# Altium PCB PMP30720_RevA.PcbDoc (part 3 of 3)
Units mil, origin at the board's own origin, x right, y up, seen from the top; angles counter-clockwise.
Board outline 4575 x 5400 mil, 4 copper layers (Top Layer, Signal Layer 1, Signal Layer 2, Bottom Layer), stack 61.6 mil thick; 223 components, 107 nets, 514 pads, 63 vias.
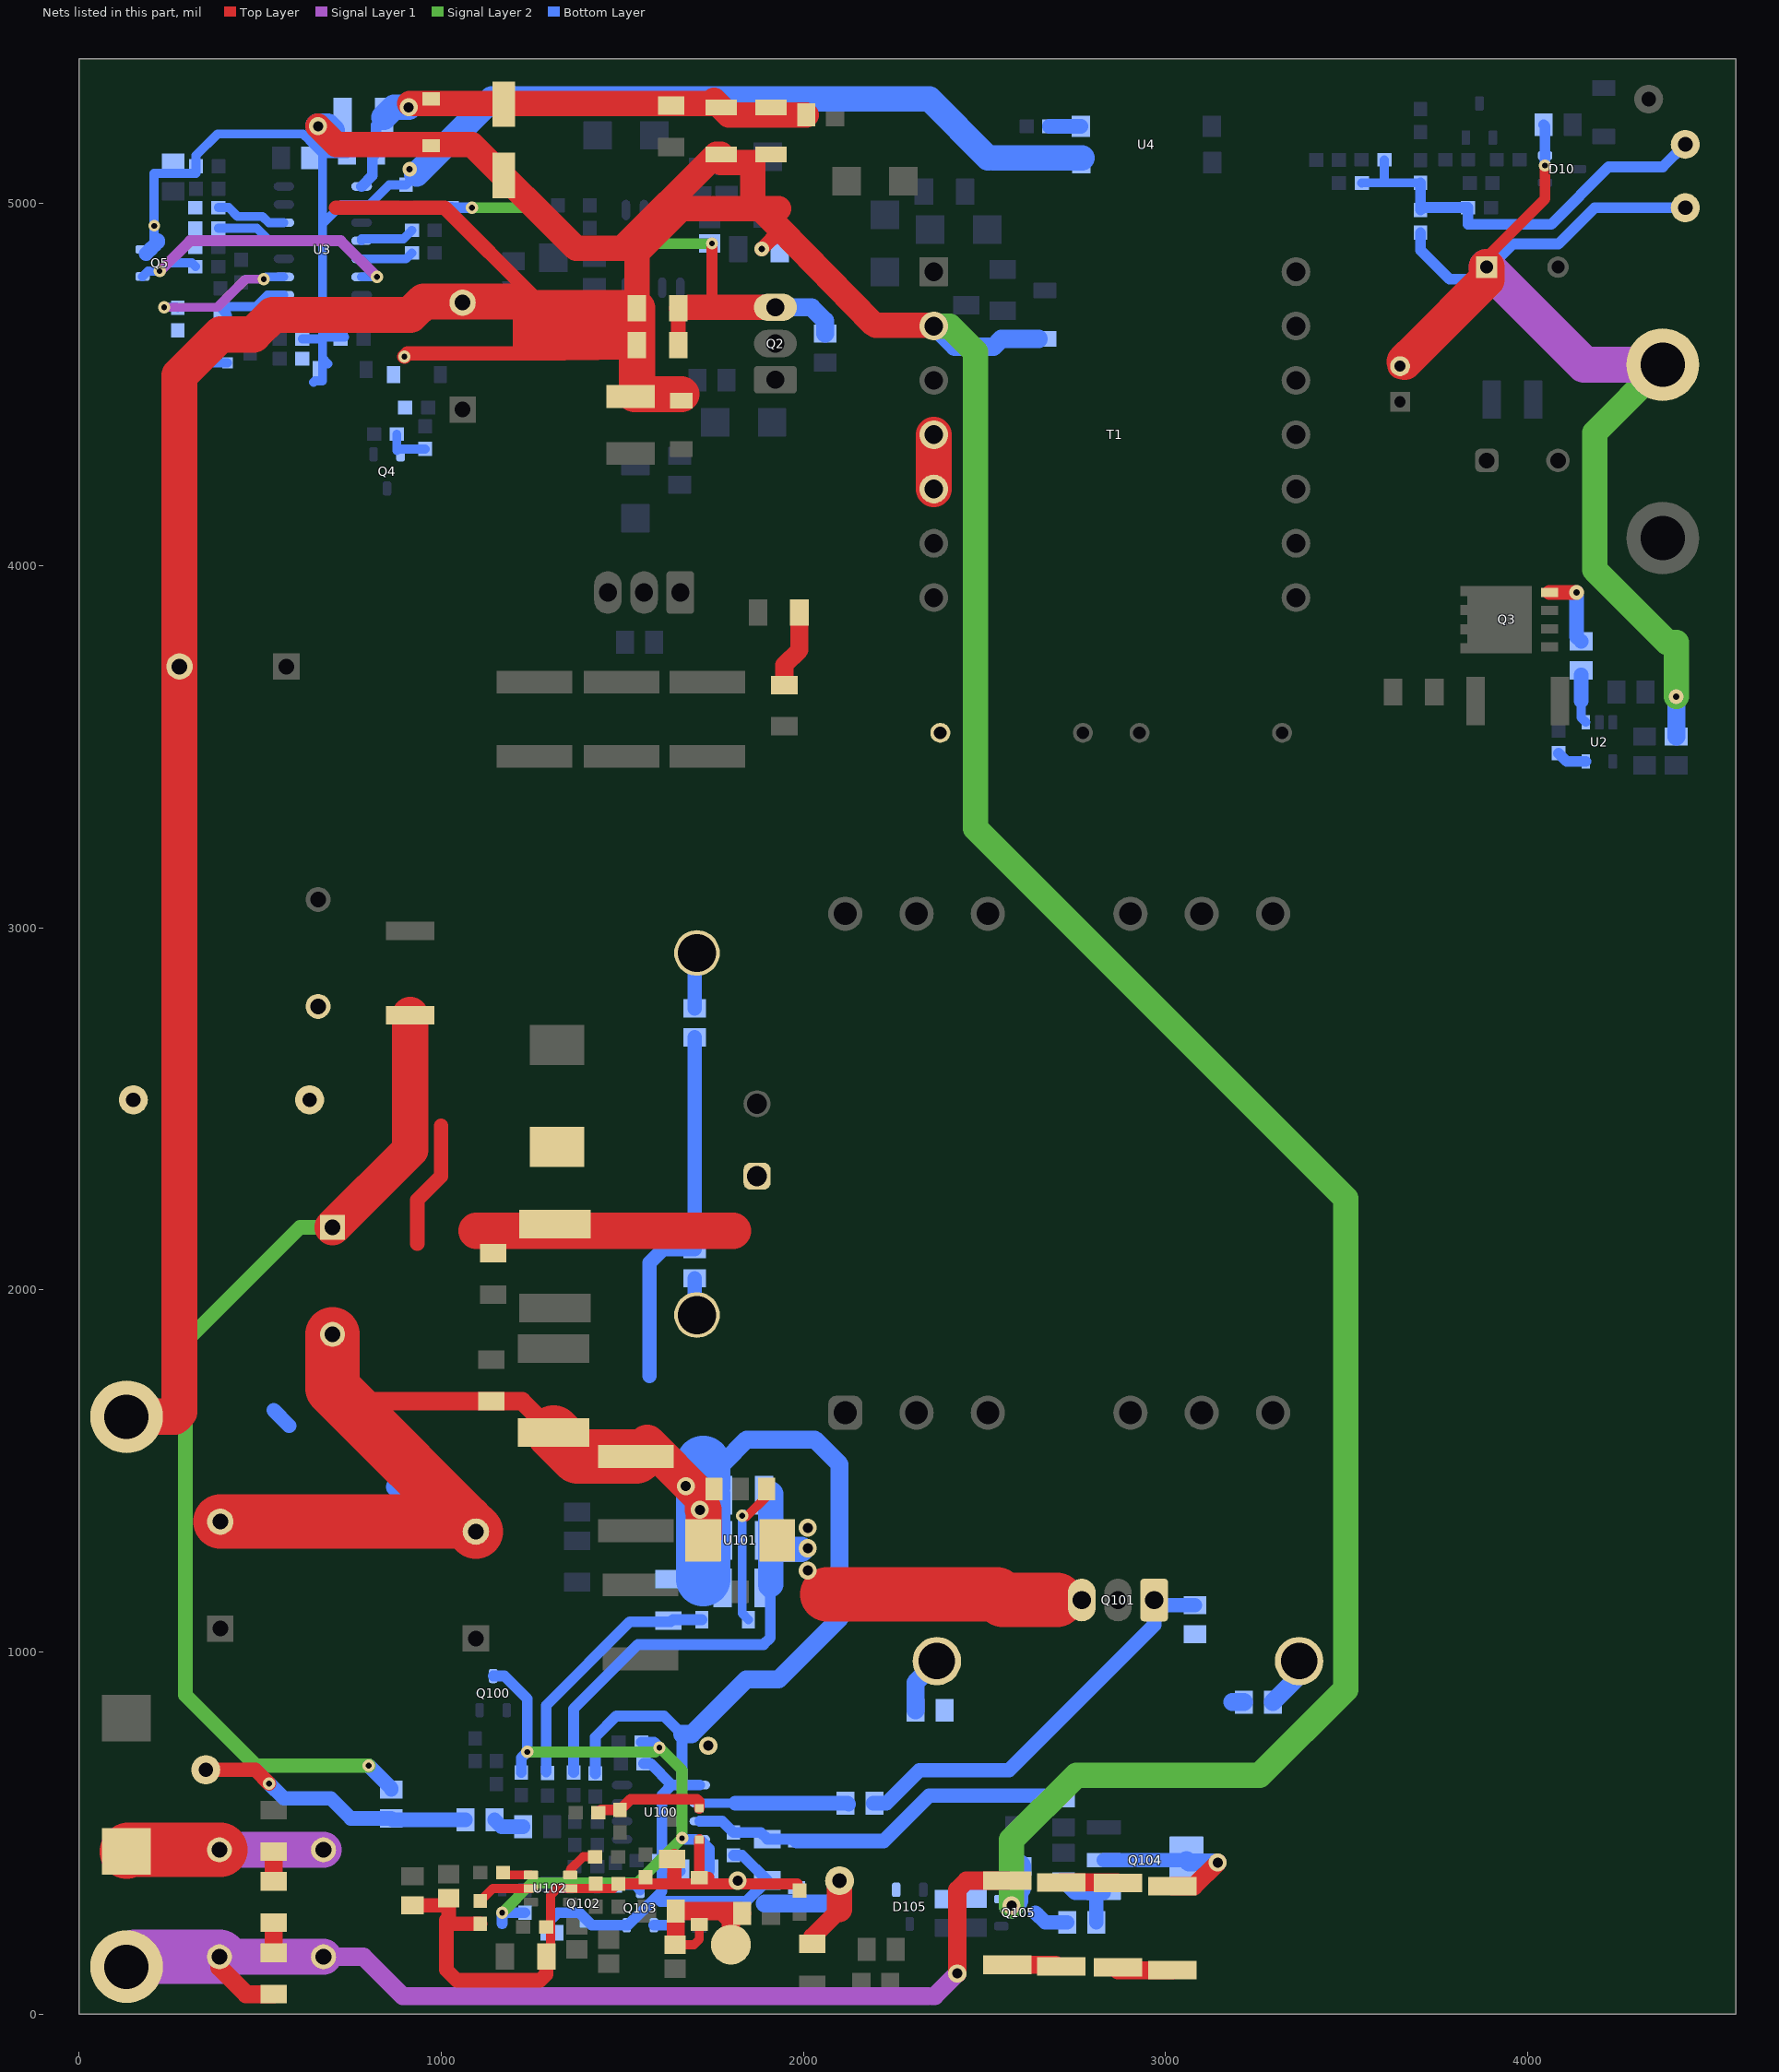
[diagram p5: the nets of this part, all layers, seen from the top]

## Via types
v1: diameter 34, hole 16, Top Layer to Bottom Layer, 36 vias
v2: diameter 50, hole 28, Top Layer to Bottom Layer, 21 vias
v3: diameter 40, hole 18, Top Layer to Bottom Layer, 5 vias
v4: diameter 32, hole 16, Top Layer to Bottom Layer, 1 vias

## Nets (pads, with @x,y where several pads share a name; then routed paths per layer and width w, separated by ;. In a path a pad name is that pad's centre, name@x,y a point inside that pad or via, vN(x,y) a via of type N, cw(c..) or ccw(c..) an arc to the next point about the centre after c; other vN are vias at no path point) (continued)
NetD104_1: D104.1 R124.2 R126.2 | length 710.7
  Bottom Layer w30: R124.2@1290.11,669.37 1290.11,852.63 1520.9,1083.43 1633.86,1083.43 1640.11,1089.68 D104.1@1719.39,1089.68
NetD104_2: D104.2 U101.1 | length 400.8
  Top Layer w25: v1@1843.54,1374.78 1898.54,1429.78 U101.1@1898.54,1450.16
  Bottom Layer w25: v1@1834.72,1380.28 v1(1831.03,1376.59) 1831.03,1106.98 D104.2@1848.33,1089.68 ; v1@1834.73,1380.26 v1@1838.07,1380.26
NetD106_1: D106.1 R138.1 R141.2 | length 315.5
  Top Layer w30: R138.1@1433.98,556.25 1442.02,564.29 R141.2@1493.75,564.29 1523.21,593.75 1706.25,593.75 1712.5,587.5 D106.1@1712.5,568.62
NetD107_1: D107.1 R142.1 R145.2 R146.1 TP104.1 | length 524.7
  Top Layer w25: R142.1@1645.62,192.08 1698.33,192.08 1712.5,206.25 D107.1@1712.5,248.03
  Top Layer w50: R142.1@1645.62,192.08 1648.12,194.58 R145.2@1648.12,284.69 1775,284.69 ; TP104.1@1781.25,171.36 1800,190.11 TP104.1@1800,192.08 1800,259.69 1775,284.69 ; R146.1@1830.62,278.44 1824.37,284.69 1775,284.69
NetF100_2: F100.2 RT100.2 RT101.2 | length 548.3
  Top Layer w150: F100.2@131.25,449.37 135.77,453.89 RT100.2@387.5,453.89 RT100.2@390.18,453.89
  Signal Layer 1 w100: RT100.2@387.5,453.89 RT101.2@675,453.89
NetH100_1: H100.1 R101.2 | length 122.9
  Bottom Layer w40: R101.2@1700,2777.5 1700,2893.72 H100.1@1704.75,2898.47
NetH100_2: H100.2 R100.2 | length 136
  Bottom Layer w40: R100.2@1700,2032.5 1700,1903.22 H100.2@1704.75,1898.47
NetH101_1: H101.1 R116.2 | length 159.9
  Bottom Layer w50: R116.2@2309.78,839.52 2309.78,916.03 H101.1@2368.75,975
NetH101_2: H101.2 R117.2 | length 143.4
  Bottom Layer w50: R117.2@3296.03,861.77 3368.75,934.49 H101.2@3368.75,975
NetQ2_3: Q2.3 R8.1 R9.2 R13.2 R14.2 R29.1 | length 1495.3
  Top Layer w30: 1747.64,4713.47 v1(1747.64,4890)
  Top Layer w40: R14.2@1654.72,4609.19 R13.2@1654.72,4710.77
  Top Layer w50: R13.2@1654.72,4710.77 1657.42,4713.47 1685.14,4713.47
  Top Layer w70: 1685.14,4713.47 1747.64,4713.47 Q2.3@1922.64,4713.47
  Signal Layer 2 w30: v1(1085.14,4988.47) 1235.14,4988.47 1335.14,4888.47 v1(1747.64,4890)
  Bottom Layer w30: R29.1@1029.13,4988.91 1029.58,4988.47 v1(1085.14,4988.47)
  Bottom Layer w50: Q2.3@1922.64,4713.47 2022.64,4713.47 2060.14,4675.97 R8.1@2060.14,4640.97
NetQ3_4: Q3.4 R18.2 | length 215.3
  Top Layer w40: Q3.4@4060.02,3925.97 v3(4135.14,3925.97)
  Bottom Layer w40: v3(4135.14,3925.97) 4135.14,3803.47 R18.2@4147.64,3790.97
NetQ4_2: Q4.2 R26.1 R34.2 | length 125.6
  Bottom Layer w25: R26.1@877.49,4363.47 877.49,4317.96 881.93,4322.4 R34.2@955.76,4322.4
NetQ5_1: Q5.1 U3.6 | length 776.2
  Signal Layer 1 w30: v1(222.64,4813.47) 306.51,4897.34 722.64,4897.34 v1(822.64,4797.34)
  Bottom Layer w25: Q5.1@175.39,4798.6 190.26,4813.47 v1(222.64,4813.47) v1@219.59,4810.41 ; U3.6@780.27,4797.34 v1(822.64,4797.34)
NetQ5_3: Q5.3 R35.1 | length 65.7
  Bottom Layer w25: Q5.3@260.04,4836.01 311.59,4836.01 R35.1@321.62,4825.97
NetQ101_1: Q101.1 R110.2 R113.2 | length 1167.1
  Bottom Layer w40: R110.2@2192.61,582.8 R110.2@2196.03,582.8 2229.24,582.8 2320.33,673.89 2567.64,673.89 2968.75,1075 Q101.1@2968.75,1143.75 2982.82,1129.68 R113.2@3081.25,1129.68
NetQ101_3: Q101.3 R120.2 R127.2 R128.2 R129.2 U101.8 | length 1981.4
  Top Layer w70: 2700,1143.75 Q101.3@2768.75,1143.75
  Top Layer w150: 2065.97,1159.7 2534.72,1159.7 2550.67,1143.75 2700,1143.75
  Bottom Layer w30: R120.2@1365.57,667.4 1365.57,843.02 1543.48,1020.93 1890.11,1020.93 1908.86,1039.68 1908.86,1159.26 R127.2@1890.95,1177.18
  Bottom Layer w70: R127.2@1910.28,1186.77 R129.2@1910.28,1436.77 ; R128.2@1916.8,1283.43 v2@1993.53,1283.43
  other v2: 2012.28,1225.06 2012.28,1286.77 2012.28,1343.02
NetQ103_1: Q103.1 R119.1 | length 63.5
  Bottom Layer w30: Q103.1@1587.18,245.77 1646.77,245.77 R119.1@1649.53,243.02
NetQ103_3: Q103.3 R115.1 | length 75
  Bottom Layer w25: R115.1@1481.03,355.27 1534.77,355.27 Q103.3@1549.78,340.26
NetQ104_1: Q104.1 R131.1 R133.2 | length 217.4
  Bottom Layer w40: R133.2@2718.75,366.25 2749.97,335.03 Q104.1@2829.58,335.03 ccw(c2829.58,314.2) 2808.75,314.2 R131.1@2808.75,253.31
NetQ104_2: Q104.2 Q104.4 R130.1 | length 469
  Top Layer w50: R130.1@3018.75,353.64 3078.64,353.64 v2(3143.75,418.75)
  Bottom Layer w40: Q104.2@2829.58,425.58 Q104.4@3057.92,425.58
  Bottom Layer w50: Q104.4@3057.92,425.58 3064.75,418.75 v2(3143.75,418.75)
NetQ105_3: Q105.3 R131.2 | length 99
  Bottom Layer w40: Q105.3@2640.99,280.52 2668.2,253.31 R131.2@2728.75,253.31
NetR1_1: R1.1 R2.2 | length 217.5
  Top Layer w50: R1.1@1947.64,3670.55 1947.64,3725.97 1988.98,3767.31 R2.2@1988.98,3870.92
NetR18_1: R18.1 U2.1 | length 136.1
  Bottom Layer w25: 4147.64,3626.06 4147.64,3580.2 U2.1@4160.24,3567.6
  Bottom Layer w40: 4147.64,3626.06 R18.1@4147.64,3698.47
NetR19_1: R19.1 U2.5 | length 84.5
  Bottom Layer w30: R19.1@4085.14,3481.97 4107.78,3459.33 U2.5@4160.24,3459.33
NetR23_1: R23.1 R28.2 R30.2 R31.2 R32.2 TP6.1 | length 1174.5
  Bottom Layer w25: R31.2@3541.63,5056.78 3542.08,5057.23 3597.64,5057.23 ; R28.2@3604.13,5120.63 3604.13,5063.73 3597.64,5057.23 ; R32.2@3704.13,5057.23 3597.64,5057.23
  Bottom Layer w30: R32.2@3704.13,5057.23 R23.1@3704.13,4982.46 3710.59,4988.91 R30.2@3835.14,4988.91 3835.14,4942.97 4065.13,4942.97 4223.44,5101.28 4372.95,5101.28 TP6.1@4435.14,5163.47
NetR25_2: R25.2 R40.1 U3.10 | length 301.9
  Bottom Layer w25: R40.1@410.14,4616.47 410.14,4691.84 386.13,4715.84 488.7,4715.84 520.2,4747.34 U3.10@565.7,4747.34
NetR33_1: R33.1 U4.4 | length 86.9
  Bottom Layer w40: R33.1@2679.13,5213.47 U4.4@2766.04,5213.47
NetR37_2: R37.2 U3.13 | length 195.7
  Bottom Layer w25: R37.2@384.62,4931.97 384.62,4931.59 491.04,4931.59 525.29,4897.34 U3.13@565.7,4897.34
NetR38_2: R38.2 U3.14 | length 198.3
  Bottom Layer w25: R38.2@384.62,4988.91 413.32,4988.91 437.77,4964.46 506.64,4964.46 523.77,4947.34 U3.14@565.7,4947.34
NetR105_1: R105.1 R107.2 TP101.1 | length 774.8
  Top Layer w40: TP101.1@350,675 487.1,675 v1(525,637.1)
  Bottom Layer w40: v1(525,637.1) 565.7,596.4 694.59,596.4 750.47,540.52 R105.1@862.28,540.52 866.03,536.77 R107.2@1067.51,536.77
NetR107_1: R107.1 R108.2 | length 86.3
  Bottom Layer w40: R107.1@1147.51,536.77 1166.26,518.02 R108.2@1226.06,518.02
NetR110_1: R110.1 U100.6 | length 412.2
  Bottom Layer w25: U100.6@1714.1,582.8 1811.76,582.8
  Bottom Layer w40: 1811.76,582.8 2122.21,582.8 R110.1@2125.11,579.9
NetR112_1: R112.1 R118.2 | length 127.9
  Top Layer w50: R112.1@2568.24,136.07 R118.2@2696.19,136.07
NetR118_1: R118.1 R123.2 | length 157.1
  Top Layer w50: R118.1@2712.5,364.17 2866.68,364.17 R123.2@2868.75,362.11
NetR123_1: R123.1 R130.2 | length 150
  Top Layer w50: R123.1@2868.75,121.36 R130.2@3018.75,121.36
NetR132_1: R132.1 R137.2 | length 83.2
  Top Layer w50: R132.1@537.2,169.59 537.2,252.41 R137.2@537.5,252.71
NetR137_1: R137.1 R140.2 | length 82.3
  Top Layer w50: R137.1@537.5,366.88 R140.2@537.5,449.16
NetR139_2: R139.2 U102.5 | length 154.1
  Top Layer w25: R139.2@1107.87,312.75 1142.32,347.19 U102.5@1247.74,347.19
NetR144_2: R144.2 U102.3 | length 98.1
  Top Layer w25: U102.3@1356,384.6 1356,398.75 1391.95,434.69 R144.2@1425.05,434.69
NetR147_2: R147.2 U102.4 | length 79.5
  Top Layer w25: R147.2@1170.87,390.94 1177.21,384.6 U102.4@1247.74,384.6
NetRT2_2: RT2.2 U3.11 | length 403.1
  Signal Layer 1 w25: v1(235.14,4713.47) 382.09,4713.47 459.8,4791.18 v1(510.14,4791.18)
  Bottom Layer w25: v1(235.14,4713.47) 271.51,4713.47 RT2.2@272.54,4712.44 ; v1(510.14,4791.18) 516.3,4797.34 U3.11@565.7,4797.34
NetT1_4: T1.4 T1.5 | length 150
  Top Layer w100: T1.5@2360.14,4211.78 T1.4@2360.14,4361.78
PGND: C1.2 C2.2 C3.2 C4.2 C17.2 C18.2 C19.2 C20.2 C21.2 C23.2 C27.1 C28.2 C31.2 C32.2 C34.2 C35.2 C36.2 C37.2 C38.2 C100.2 C101.2 C104.2 C105.2 C106.2 C107.2 C108.2 C112.2 C113.2 C114.2 C115.2 C116.2 C117.2 C118.2 C119.2 C120.2 C121.2 C122.2 C123.2 C124.2 D9.2 D102.2 D105.1 D106.2 D107.2 DZ1.2 Dz2.2 Q5.2 Q102.3 Q103.2 Q105.2 R10.1 R13.1 R14.1 R22.1 R37.1 R38.1 R39.1 R40.2 R100.1 R101.1 R104.1 R106.1 R113.1 R116.1 R117.1 R122.1 R126.1 R127.1 R128.1 R129.1 R139.1 R143.1 R148.1 R149.1 R150.1 RT2.1 T1.2 TP2.1 TP102.1 TP103.1 U3.2 U4.3 U100.5 U101.3 U101.7 U102.2 | length 28880.8
  Top Layer w25: C117.2@1290.21,159.69 1301.87,171.36 1301.87,328.44 1320.62,347.19 U102.2@1356,347.19 1476.62,347.19 C121.2@1489.37,359.94
  Top Layer w30: C121.2@1489.37,359.94 1739.37,359.94 ; D107.2@1712.5,378.36 D106.2@1712.5,482.01 ; 1739.37,378.2 1739.37,359.94 ; C122.2@1983.37,359.94 1739.37,359.94
  Top Layer w40: 710.14,4988.47 1010.14,4988.47 1260.14,4738.47 1260.14,4710.77 ; v1(898.38,4577.26) 907.53,4586.42 1338.83,4586.42 R14.1@1530.71,4588.47 ; R150.1@920.62,300.94 1001.58,300.94 C124.2@1020.62,319.98 1020.62,265.94 1014.37,259.69 ; R139.1@1107.87,249.75 1024.31,249.75 1014.37,259.69 ; C117.2@1290.21,159.69 1290.21,110.53 1273.43,93.75 1042.82,93.75 1014.37,122.19 1014.37,259.69 ; 1643.75,366.88 C123.2@1643.75,436.34 ; v3(1885.14,4874.43) 1934.09,4923.39 1934.09,4931.9
  Top Layer w50: 759.82,1668.72 784.01,1692.91 R106.1@1138.09,1692.91 1223.62,1692.91 C106.2@1310.28,1606.25 ; 1222.64,4597.29 1222.81,4675.94 ; C118.2@2025,194.59 2025,213.93 2100,288.93
  Top Layer w70: v2(660.14,5213.47) 710.14,5163.47 1085.14,5163.47 1372.64,4875.97 1499.21,4875.97 1759.25,5136.01 C20.2@1772.64,5136.01 ; R13.1@1540.55,4710.77 1540.55,4863.47 1663.32,4986.23 1860.14,4986.23 ; 1772.64,5113.47 1860.14,5113.47 1860.14,4986.23 ; 1874.81,4992.5 1880.94,4986.23 ; 1931.9,4986.23 1880.94,4986.23 ; 2100,288.93 TP103.1@2100,368.75 ; 2190.55,4669.74 1934.09,4931.9 1880.94,4986.23 ; 2200.88,4663.47 2358.45,4663.47 T1.2@2360.14,4661.78 ; 1860.14,4986.23 1880.94,4986.23
  Top Layer w100: TP102.1@131.25,1650 263.98,1650 277.36,1663.39 277.13,1663.39 277.13,3721.34 C1.2@277.36,3721.58 277.36,4525 390.83,4638.47 481.32,4638.47 535.14,4692.28 914.33,4692.28 951.66,4729.62 1193.99,4729.62 ; 1251.64,4650.97 1485.14,4650.97 ; 1260.14,4710.77 R13.1@1540.55,4710.77 R14.1@1540.55,4609.19 C3.2@1540.55,4485.12 ; C3.2@1534.45,4473.34 C4.2@1663.32,4473.34 ; C104.2@1537.5,1539.86 C104.2@1567.26,1539.86 ; 1569.03,1578.1 1715.88,1431.25 ; v2@1722.51,1392.97 v2@1722.53,1395.92 ; U101.7@1725,1317.67 v2@1725,1393.02
  Top Layer w150: C100.2@390.18,1360.14 1068.41,1360.14 ; C105.2@700,1877.36 700,1728.54 759.82,1668.72 1068.41,1360.14 ; C101.2@1095.87,1332.68 1068.41,1360.14 ; C106.2@1310.28,1606.25 1376.67,1539.86 C104.2@1537.5,1539.86
  Signal Layer 2 w70: T1.2@2360.14,4661.78 2403.74,4661.78 2475,4590.52 2475,3275 3497.13,2252.87 3497.13,897.13 3259.73,659.73 2753.67,659.73 2575,481.07 v2(2575,300)
  Bottom Layer w25: 201.33,4877.69 207.44,4883.8 v4(207.44,4938.47) 207.44,5083.4 323.14,5083.4 323.14,5132.97 382.38,5192.21 618.9,5192.21 637.64,5173.47 637.64,5172.47 672.64,5137.47 ; 363.44,4560.47 R40.2@410.14,4560.47 ; R22.1@616.63,4625.97 672.64,4625.97 ; 647.64,4506.67 651.67,4510.71 672.64,4510.71 672.64,4572.15 ; 686.87,4557.91 672.64,4572.15 ; C27.1@733.76,4631.04 680.06,4631.04 674.99,4625.97 672.64,4625.97 ; C34.2@740.27,5138.47 739.27,5137.47 672.64,5137.47 ; 932.38,5081.2 C38.2@903.09,5051.91 856.15,5051.91 801.57,4997.34 U3.2@780.27,4997.34 725.15,4997.34 672.64,4944.82 ; 672.64,4572.15 672.64,4625.97 ; 672.64,4625.97 672.64,4944.82 ; 672.64,4944.82 672.64,5137.47
  Bottom Layer w30: 1306.61,265.52 1321.37,280.27 1381.03,280.27 1415.52,245.77 Q103.2@1512.37,245.77 1515.67,245.77 1593.72,323.82 ; C115.2@1425.57,664.29 1425.57,765.35 1483.86,823.65 1615.11,823.65 1665.11,773.65 1665.11,632.8 ; C112.2@1559.11,692.4 1577.16,692.4 1636.76,632.8 ; C113.2@1660.57,395.3 1650.97,404.9 1609.35,404.9 ; U100.5@1714.1,632.8 1665.11,632.8 ; C107.2@1806.82,438.8 1831.23,438.8 C108.2@1900.57,369.46 1842.87,311.77 1605.78,311.77 1593.72,323.82 ; 1593.72,323.82 1609.35,339.45 1609.35,404.9 ; 1609.35,404.9 1609.35,605.39 1636.76,632.8 ; 1636.76,632.8 1665.11,632.8
  Bottom Layer w40: Q5.2@185.24,4861.6 201.33,4877.69 ; 207.44,4883.8 217.43,4893.79 217.43,4897.34 ; 537.28,1668.02 580.17,1625.12 ; 1575,1762.62 1575,2075 1612.5,2112.5 R100.1@1700,2112.5 R101.1@1700,2697.5
  Bottom Layer w50: 872.22,1456.06 1009.72,1318.56 ; 1665.11,773.65 1691.48,773.65 1842.1,924.27 1931.03,924.27 2099.78,1093.02 2099.78,1518.02 2031.03,1586.77 1843.53,1586.77 1779.21,1522.45 1723.35,1522.45 ; 1893.53,305.52 2099.93,305.3 2103.19,305.3 ; T1.2@2360.14,4661.78 2417.22,4604.69 C17.2@2450,4604.69 2525,4604.69 2546.59,4626.28 C18.2@2650,4626.28 ; 3184.27,861.77 R117.1@3216.03,861.77
  Bottom Layer w70: v2(660.14,5213.47) 686.27,5213.47 698.77,5200.97 ; 932.38,5081.2 1139.65,5288.47 2347.64,5288.47 2509.4,5125.97 ; 2525,5125.97 U4.3@2769.39,5125.97 ; v2(2575,300) 2578.12,303.12 2578.12,306.56 2585.78,314.22 2585.78,327.75 2578.93,334.6 2593.75,349.41 C119.2@2593.75,407.88
  Bottom Layer w150: 1723.35,1201.04 1723.35,1433.43 ; 1723.35,1458.43 1723.35,1522.45
  other v2: 1818.75,368.75 1737.5,741.48 1714.1,1393.02 1675.45,1458.43
  other v3: 912.88,5095.06
PWMH: R12.1 U3.5 | length 145.6
  Bottom Layer w25: U3.5@780.27,4847.34 903.09,4847.34 R12.1@919.22,4863.47
PWML: R11.1 U3.4 | length 153.9
  Bottom Layer w25: U3.4@780.27,4897.34 780.27,4902.54 895.79,4902.54 R11.1@919.22,4925.97
VDD_1: C19.1 C20.1 C32.1 C34.1 C35.1 D9.1 R4.1 R20.1 U3.1 | length 1410.8
  Top Layer w70: v2@912.88,5276.77 1745.61,5276.77 1753.7,5284.86 C20.1@1772.64,5265.93 1793.7,5244.86 R20.1@2007.64,5244.86
  Bottom Layer w30: U3.1@780.27,5047.34 810.14,5077.21 810.14,5128.34 C34.1@820.27,5138.47 820.27,5216.51 C35.1@842.22,5238.47
  Bottom Layer w70: C35.1@842.22,5238.47 869.68,5265.93 v2(910.14,5265.93)
VDD_DCDC: C107.1 C108.1 D102.1 R136.1 U100.7 | length 1050.4
  Bottom Layer w30: U100.7@1714.1,532.8 1775.82,532.8 C107.1@1806.82,501.79 1882.41,501.79 C108.1@1900.57,483.63 1975.94,483.63 cw(c1975.94,478.32) D102.1@1981.25,478.32
  Bottom Layer w40: D102.1@1981.25,478.32 2222.07,478.32 2347.18,603.43 R136.1@2689.31,603.43
Vin: R112.2 R132.2 RT100.1 RT101.1 TP100.1 | length 3000.2
  Top Layer w50: RT100.1@387.5,158.61 387.5,129.28 461.37,55.41 R132.2@537.2,55.41 ; v2(2425,112.5) 2425,343.75 2450.1,368.85 R112.2@2563.36,368.85
  Top Layer w100: TP100.1@131.25,131.25 cw(c158.61,131.25) TP100.1@158.61,158.61
  Signal Layer 1 w50: RT101.1@675,158.61 785.14,158.61 893.75,50 2342.62,50 ; 2355.32,50 2362.5,50 v2(2425,112.5)
  Signal Layer 1 w100: RT100.1@387.5,158.61 RT101.1@675,158.61
  Signal Layer 1 w150: TP100.1@131.25,131.25 cw(c158.61,131.25) 158.61,158.61 RT100.1@387.5,158.61
Vout: C14.1 D10.2 L1.2 R23.2 R24.2 R42.1 TP3.1 TP5.1 | length 3591.9
  Top Layer w30: C14.1@3886.71,4824.48 3886.71,4852.16 4047.89,5013.33 v1(4047.89,5104.95)
  Top Layer w70: L1.2@3647.64,4550.97 3698.13,4601.46
  Top Layer w100: L1.2@3660.14,4563.47 3698.13,4601.46 3886.71,4790.04 C14.1@3886.71,4824.48
  Signal Layer 1 w100: C14.1@3886.71,4824.48 4156.19,4555 TP3.1@4372.64,4555
  Signal Layer 2 w70: TP3.1@4372.64,4555 4185.14,4367.5 4185.14,3988.47 4385.14,3788.47 4410.14,3788.47 v3(4410.14,3638.47)
  Bottom Layer w30: R23.2@3704.13,4919.47 3704.13,4871.04 3784,4791.18 3861.38,4791.18 3958.67,4888.47 4084.69,4888.47 4184.69,4988.47 TP5.1@4435.14,4988.47 ; R42.1@4043.71,5217.77 4047.89,5213.59 D10.2@4047.89,5132.46 v1(4047.89,5104.95)
  Bottom Layer w50: R24.2@4410.14,3528.47 v3(4410.14,3638.47)
Vout_DCDC: C103.1 C105.1 D100.1 D101.1 R103.2 R105.2 RF1.1 RT1.1 TP1.1 | length 3926.4
  Top Layer w40: 933.93,2128.01 933.93,2248.4 999.78,2314.25 999.78,2452.96
  Top Layer w100: C105.1@700,2172.64 914.3,2386.94 RF1.1@914.3,2758.86 ; 1097.22,2163.35 1805.39,2163.35
  Signal Layer 2 w40: C105.1@700,2172.64 610.14,2172.64 293.75,1856.25 293.75,881.25 488.23,686.77 v1(799.78,686.77)
  Bottom Layer w40: v1(799.78,686.77) 862.28,624.27 R105.2@862.28,620.52
VREF1: C113.1 D103.2 Q100.3 R109.2 R111.2 R125.1 U100.8 | length 1855.9
  Signal Layer 2 w30: v1(1168.53,280.52) 1250.51,362.5 1541.47,362.5 v1(1665.11,486.15) 1665.11,673.65 v1(1602.61,736.15) 1590.73,724.27 v1(1237.71,724.27)
  Bottom Layer w30: Q100.3@1143.53,934.01 1174.78,934.01 1237.71,871.08 v1(1237.71,724.27) 1221.36,707.92 R125.1@1221.36,667.4 ; D103.2@1168.53,250.15 v1(1168.53,280.52) 1230.78,280.52 R109.2@1231.03,280.27 ; R111.2@1552.86,751.15 1587.61,751.15 v1(1602.61,736.15) ; v1(1665.11,486.15) 1671.36,486.15 1674.71,482.8 U100.8@1714.1,482.8 1740.57,456.33 C113.1@1740.57,395.3
pads on no net: D105.2 L100.1 L100.6 L100.7 L100.8 L100.9 L100.10 L100.11 L100.12 T1.7 T1.8 T1.11 T1.14 U101.2 U101.4 U101.5 U101.6

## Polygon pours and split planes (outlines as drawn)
NetC103_2 on Top Layer "TOP_LAYER_NETC103_2_P130" (solid, remove dead copper, pour order 130): 1421.38,1986.98 cw(c1421.38,1958.36) 1450,1958.36 1450,1810.63 cw(c1426.87,1810.63) 1426.87,1787.5 1094.83,1787.5 cw(c1094.83,1800) 1082.33,1800 1082.33,1961.44 cw(c1107.87,1961.44) 1107.87,1986.98
NetD107_1 on Top Layer "TOP_LAYER_NETD107_1_P128" (solid, remove dead copper, pour order 128): 1618.67,309.79 1617.08,308.2 1617.08,175 1708.25,175 1733.25,200 1725,208.25 1725,311.77 1625,311.77
Vout_DCDC on Top Layer "TOP_LAYER_VOUT_DCDC_P126" (solid, remove dead copper, pour order 126): 537.17,2662.74 537.17,2780.55 cw(c581.62,2780.55) 581.62,2825 1045.87,2825 cw(c1045.87,2775) 1095.87,2775 1095.87,2128.41 cw(c995.87,2128.41) 995.87,2028.41 580.85,2028.41 cw(c580.85,2071.75) 537.5,2071.75
NetC1_1 on Top Layer "TOP_LAYER_NETC1_1_P124" (solid, remove dead copper, pour order 124): 537.17,4452.98 cw(c583.73,4452.98) 583.73,4499.53 997.31,4499.53 cw(c997.31,4399.53) 1097.31,4399.53 1097.31,2981.31 cw(c1039.57,2981.31) 1039.57,2923.56 603.32,2923.56 cw(c603.32,2989.71) 537.17,2989.71
PGND on Top Layer "TOP_LAYER_PGND_P122" (solid, remove dead copper, pour order 122): 26.68,1700 25,1701.68 25,5288.47 cw(c75,5288.47) 75,5338.47 703.15,5338.47 cw(c703.15,5291.62) 750,5291.62 750,4650 cw(c650,4650) 650,4550 557.79,4550 ccw(c557.79,4467.21) 475,4467.21 475,1704.2 ccw(c479.2,1704.2) 479.2,1700
NetC1_1 on Top Layer "TOP_LAYER_NETC1_1_P116" (solid, remove dead copper, pour order 116): 2239.41,3648.5 2239.41,3338.47 1036.16,3338.47 cw(c1036.16,3375.97) 998.66,3375.97 998.66,3501.99 cw(c1048.15,3513.98) 1036.16,3563.47 2097.64,3563.47 ccw(c2110.14,3550.97) 2097.64,3538.47
NetC1_1 on Top Layer "TOP_LAYER_NETC1_1_P114" (solid, remove dead copper, pour order 114): 1059.95,3670.55 1064.67,3665.83 1059.95,3713.47 1064.67,3899.31 1410.14,4261.6 1577.26,4261.6 ccw(c1577.26,4288.47) 1604.13,4288.47 1604.13,4349.79 ccw(c1585.14,4349.79) 1585.14,4368.79 1404.81,4368.79 cw(c1404.81,4438.46) 1335.14,4438.47 1335.14,4450.97 ccw(c1285.14,4450.97) 1285.14,4500.97 610.99,4500.97 ccw(c610.99,4493.62) 603.64,4493.62 ccw(c589.41,4439.35) 535.14,4425.11 535.14,4261.6 cw(c548.79,4208.4) 603.64,4211.03 947.27,3826.15 ccw(c1003.58,3808.4) 971.99,3758.52 cw(c939.55,3726.08) 971.99,3693.63
NetQ2_3 on Top Layer "TOP_LAYER_NETQ2_3_P112" (solid, remove dead copper, pour order 112): 1667.62,4797.49 1670.06,4799.93 1830.12,4799.93 1830.12,4602.26 cw(c1805.12,4602.26) 1805.12,4577.26 1667.08,4577.26 cw(c1667.08,4614.23) 1630.12,4614.23 1630.12,4772.49 cw(c1655.12,4772.49) 1655.12,4797.49
NetC5_2 on Top Layer "TOP_LAYER_NETC5_2_P110" (solid, remove dead copper, pour order 110): 1897.64,3800.97 1847.64,3750.97 1847.64,3638.47 cw(c1835.14,3638.47) 1835.14,3625.97 1167.1,3625.97 cw(c1167.1,3638.47) 1154.6,3638.47 1154.6,3770.43 cw(c1185.14,3770.43) 1185.14,3800.97
NetC1_1 on Top Layer "TOP_LAYER_NETC1_1_P108" (solid, remove dead copper, pour order 108): 910.14,3783.94 cw(c910.14,3753.3) 940.78,3753.3 940.78,3382.52 ccw(c984.84,3382.52) 984.84,3338.47 1060.14,3338.47 ccw(c1060.14,3350.97) 1072.64,3350.97 1072.64,3738.47 ccw(c1035.14,3738.47) 1035.14,3775.97
NetR1_1 on Top Layer "TOP_LAYER_NETR1_1_P106" (solid, remove dead copper, pour order 106): 1947.64,3906.35 1947.64,3773.44 cw(c1925.17,3773.44) 1925.17,3750.97 1922.64,3750.97 ccw(c1922.64,3740.53) 1912.2,3740.53 1912.2,3625.97 cw(c1914.11,3625.97) 1914.11,3627.87 2031.66,3627.87 ccw(c2031.66,3656.35) 2060.14,3656.35 2060.14,3913.47 ccw(c2035.14,3913.47) 2035.14,3938.47 1979.75,3938.47 ccw(c1979.75,3906.35)
NetC16_2 on Top Layer "TOP_LAYER_NETC16_2_P008" (solid, remove dead copper, pour order 8): 4010.41,3740.72 cw(c3992.49,3740.72) 3992.49,3722.8 3635.41,3722.8 cw(c3628.05,3748.07) 3602.78,3740.72 3602.78,4088.47 3992.49,4088.47 cw(c3980.47,4058.53) 4010.41,4046.51
GND1 on Top Layer "TOP_LAYER_GND1_P104" (solid, remove dead copper, pour order 104): 3397.64,5300.97 cw(c3435.14,5300.97) 3435.14,5338.47 4460.14,5338.47 cw(c4460.14,5300.97) 4497.64,5300.97 4497.64,3475 cw(c4448.82,3475) 4448.82,3426.18 3464.13,3426.18 cw(c3464.13,3475) 3415.31,3475
NetC5_2 on Top Layer "TOP_LAYER_NETC5_2_P102" (solid, remove dead copper, pour order 102): 1910.14,3843.64 1910.14,3907.83 ccw(c1883.3,3907.83) 1883.3,3934.66 1804.49,3934.66 ccw(c1804.49,3900.97) 1770.8,3900.97 1770.8,3876.3 cw(c1722.64,3876.3) 1722.64,3828.14 ccw(c1722.64,3803.14) 1697.64,3803.14 1697.64,3788.47 ccw(c1710.14,3788.47) 1710.14,3775.97 1837.62,3775.97
PGND on Top Layer "TOP_LAYER_PGND_P100" (solid, remove dead copper, pour order 100): 2347.64,5338.47 2347.64,4638.47 cw(c2335.14,4638.47) 2335.14,4625.97 2195.05,4625.97 1810.09,4961.07 1667.62,4961.07 1560.14,4863.47 1550.39,4638.47 597.64,4638.47 cw(c597.63,4664.55) 571.55,4664.55 571.55,5287.38 cw(c622.64,5287.38) 622.64,5338.47
NetC13_1 on Top Layer "TOP_LAYER_NETC13_1_P098" (solid, remove dead copper, pour order 98): 3935.14,4265.07 cw(c3907.41,4265.07) 3907.41,4237.34 3472.24,4237.34 cw(c3472.24,4274.44) 3435.14,4274.44 3435.14,4398.92 ccw(c3397.64,4398.92) 3397.64,4436.42 3369.9,4436.42 cw(c3369.9,4496.18) 3310.14,4496.18 3310.14,4677.57 cw(c3347.64,4677.57) 3347.64,4715.07 3371.4,4715.07 cw(c3371.4,4650.97) 3435.5,4650.97 ccw(c3531.47,4650.97) 3531.47,4555 3535.14,4555
PGND on Top Layer "TOP_LAYER_PGND_P024" (solid, remove dead copper, pour order 24): 1200,1250 ccw(c1200,1312.5) 1262.5,1312.5 1262.5,1366.49 cw(c1333.51,1366.49) 1333.51,1437.5 1750,1437.5 ccw(c1722.43,1477.57) 1762.5,1505.14 1762.5,1675 ccw(c1718.75,1675) 1718.75,1718.75 1020.34,1723.41 cw(c1020.34,1787.5) 956.25,1787.5 956.25,1922.22 ccw(c909.72,1922.22) 909.72,1968.75 56.25,1968.75 ccw(c56.25,1937.5) 25,1937.5 25,1293.75 ccw(c68.75,1293.75) 68.75,1250
Vout_DCDC on Top Layer "TOP_LAYER_VOUT_DCDC_P014" (solid, remove dead copper, pour order 14): 675,2033.43 cw(c646.62,2107.41) 572.64,2079.04 572.64,2495.93 cw(c655.07,2475.99) 675,2558.43 1709.72,2558.43 cw(c1709.72,2495.93) 1772.22,2495.93 1967.83,2233.43 1967.83,2079.04 cw(c1922.22,2079.03) 1922.22,2033.43
NetQ101_3 on Top Layer "TOP_LAYER_NETQ101_3_P012" (solid, remove dead copper, pour order 12): 2587.75,1195.93 2347.22,1483.43 ccw(c2286.86,1423.07) 2286.86,1508.43 1858.97,1508.43 ccw(c1858.97,1495.93) 1846.47,1495.93 1846.47,1102.97 ccw(c1866.02,1102.97) 1866.02,1083.43 2554.57,1083.43 ccw(c2554.57,1113.57) 2584.72,1113.57
PGND on Bottom Layer "BOTTOM_LAYER_PGND_P096" (solid, remove dead copper, pour order 96): 2771.85,5350 cw(c2766.49,5318.85) 2797.64,5313.48 2797.64,5000.97 cw(c2760.14,5000.97) 2760.14,4963.47 2110.14,4963.47 ccw(c2141.39,4857.22) 2035.14,4825.97 2035.14,4292.54 cw(c1980.63,4268.47) 1962.29,4211.78 75.75,4211.78 cw(c122.69,4301.01) 22.64,4313.47 22.64,5260.52 cw(c93.9,5278.72) 75.75,5350
GND1 on Bottom Layer "BOTTOM_LAYER_GND1_P094" (solid, remove dead copper, pour order 94): 4500,3350 cw(c4475,3350) 4475,3325 3450,3325 cw(c3436.32,3363.68) 3397.64,3350 3397.64,5313.47 cw(c3422.64,5313.47) 3422.64,5338.47 4447.64,5338.47 cw(c4447.64,5288.47) 4497.64,5288.47
PGND on Bottom Layer "BOTTOM_LAYER_PGND_P022" (solid, remove dead copper, pour order 22): 443.53,1700 cw(c481.03,1737.5) 443.53,1775 1987.28,1775 cw(c1949.78,1737.5) 1987.28,1700 1987.28,1605.52 ccw(c2006.03,1605.52) 2006.03,1586.77 3162.28,1586.77 cw(c3187.76,1524.53) 3250,1550 3250,93.97 cw(c3174.78,106.46) 3162.28,31.25 506.25,31.25 cw(c506.25,93.97) 443.53,93.97
NetQ101_3 on Bottom Layer "BOTTOM_LAYER_NETQ101_3_P018" (solid, remove dead copper, pour order 18): 1853.47,1489.68 cw(c1884.72,1489.68) 1884.72,1520.93 1981.03,1520.93 cw(c1996.75,1486.95) 2024.78,1511.77 2024.78,1105.52 cw(c2002.86,1121.23) 1993.53,1095.93 1877.97,1095.93 cw(c1877.97,1120.43) 1853.47,1120.43
PGND on Signal Layer 1 "SIGNAL_LAYER_1_PGND_P120" (solid, remove dead copper, pour order 120): 2362.73,5314.25 cw(c2362.73,5276.75) 2400.23,5276.75 2400.23,3339.25 cw(c2362.73,3339.25) 2362.73,3301.75 862.73,3301.75 cw(c862.73,3326.75) 837.73,3326.75 837.73,4064.25 ccw(c787.73,4064.25) 787.73,4114.25 100,4114.25 cw(c75.11,4153.9) 35.46,4129.02 35.46,5249.72 cw(c100,5249.72) 100,5314.25
GND1 on Signal Layer 1 "SIGNAL_LAYER_1_GND1_P118" (solid, remove dead copper, pour order 118): 3397.64,5313.47 cw(c3422.64,5313.47) 3422.64,5338.47 4472.64,5338.47 cw(c4472.64,5313.47) 4497.64,5313.47 4497.64,3500 cw(c4472.64,3500) 4472.64,3475 3450,3475 cw(c3436.32,3513.68) 3397.64,3500
Vout on Signal Layer 1 "SIGNAL_LAYER_1_VOUT_P002" (solid, remove dead copper, pour order 2): 4497.15,4463.47 4459.65,4463.47 3585.14,4465.76 cw(c3585.14,4478.26) 3572.64,4478.26 3572.64,4581.04 cw(c3622.64,4581.04) 3622.64,4631.04 3693.24,4631.04 ccw(c3693.24,4697.93) 3760.14,4697.93 3760.14,4830.02 cw(c3810.14,4830.02) 3810.14,4880.02 3922.4,4880.02 cw(c3922.4,4838.47) 3963.96,4838.47 3963.96,4703.71 ccw(c3991.7,4703.71) 3991.7,4675.97 4459.65,4675.97 cw(c4459.65,4638.47) 4497.15,4638.47 4497.15,4508.67 cw(c4451.95,4508.67) 4451.95,4463.47
NetC100_1 on Signal Layer 1 "SIGNAL_LAYER_1_NETC100_1_P090" (solid, remove dead copper, pour order 90): 203.12,1096.88 cw(c256.25,1084.38) 268.75,1137.5 281.25,1150 2106.25,1150 2750,1718.75 cw(c2781.25,1718.75) 2781.25,1750 3175,1750 cw(c3175,1718.75) 3206.25,1718.75 3206.25,1650 cw(c3175,1650) 3175,1618.75 3068.75,1618.75 2253.12,803.12 303.12,803.12 cw(c303.12,903.12) 203.12,903.12
PGND on Signal Layer 2 "SIGNAL_LAYER_2_PGND_P092" (solid, remove dead copper, pour order 92): 968.75,1556.25 ccw(c968.75,1493.75) 906.25,1493.75 906.25,112.5 ccw(c968.75,112.5) 968.75,50 2010.71,50 ccw(c2010.71,91.85) 2052.56,91.85 2052.56,1493.75 ccw(c2004.41,1508.09) 2018.75,1556.25

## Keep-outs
Top Layer:
  region: 591.14,4925.97 ccw(c591.14,4938.47) 603.64,4938.47 603.64,5008.41 ccw(c586.09,5008.41) 586.09,5025.97 539.82,5025.97 ccw(c539.82,5013.47) 527.32,5013.47 527.32,4925.97
  region: 576.31,4925.97
  region: 597.64,4946.1
Signal Layer 1:
  circle w10: c565.7,4688.47 r23.98
  region: 595.82,5025.97 517.1,5025.97 517.1,4925.97 595.82,4925.97
Keep-Out Layer:
  text ".Layer_Name" at 577,-858.49 h60

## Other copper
Top Layer:
  text ".Layer_Name" at 577,-858.49 h60
Bottom Layer:
  text ".Layer_Name" at 577,-858.49 h60

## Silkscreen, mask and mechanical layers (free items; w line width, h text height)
Top Overlay:
  lines w10: 1087.5,200 1125.5,200 1150,224.5 1168.53,224.5 1187,224.5 ; 1176.24,240.39 1187,229.63 1187,224.5 ; 1490.55,250.74 1497.69,257.88 1509.13,257.88 ; 1527.78,257.88 1509.13,257.88 ; 1550,207.33 1550,217.01 1509.13,257.88 ; 1187,224.5 1176.24,213.74 1187,224.5
  text "'.PRJ_Number'.PCB_Rev" at 2543.53,205.52 h30
  text "PMP30720_RevA" at 3375,100 h150
  text ".Layer_Name" at 577,-858.49 h30
Bottom Overlay:
  lines w10: 1106.25,412.5 1269.44,412.5 1292.15,425 1325,446.33 1306.06,465.27 ; 1312.5,418.06 1325,440.4
  text ".Layer_Name" at 577,-858.49 h30
Top Paste:
  text ".Layer_Name" at 577,-858.49 h60
Bottom Paste:
  text ".Layer_Name" at 577,-858.49 h60
Top Solder:
  text ".Layer_Name" at 577,-858.49 h60
  text ".Layer_Name" at 577,-858.49 h60
Bottom Solder:
  text ".Layer_Name" at 577,-858.49 h60
Drill Guide:
  text ".Layer_Name" at 577,-858.49 h60
M1 Board Outline:
  the board outline again, w10
  text ".Layer_Name" at 577,-858.49 h60
M2 Board Dimensions:
  rectangle: 0,-275 125,-150
  rectangle: 125,-400 500,-275
  lines w7: 0,-275 1000,-275 ; 125,-400 125,-150 ; 250,-400 250,-150 ; 500,-400 500,-150 ; 750,-400 750,-150 ; 0,-400 1000,-400 1000,-150 0,-150 0,-400
  text ".Layer_Name" at 577,-858.49 h60
M3 3D STEP Top:
  text ".Layer_Name" at 577,-858.49 h60
M4 3D STEP Bottom:
  text ".Layer_Name" at 577,-858.49 h60
M5 Assembly Top:
  lines w10: -292,-930.17 6308,-930.17 ; -292,-726.83 6310,-726.83 ; -292,-523.5 -292,-1133.5 3713,-1133.5 6310,-1133.5 6310,-523.5 -291.5,-523.5 -291.5,-1133.5 1284,-1133.5 ; 2173,-1133.5 2173,-523.5 ; 3440,-726.83 3440,-523.5 ; 4280,-726.83 4280,-523.5 ; 4902,-1140 4902,-937.17
  text "COMPONENTS MARKED 'DNP' SHOULD NOT BE POPULATED." at 1153.5,-318.5 h60
  text "ASSEMBLY VARIANT:" at 1153,-434 h60
  text ".VariantName" at 2189,-434 h60
  text "PCB VIEWED FROM TOP SIDE" at -228.5,-655.67 h60
  text "BOARD #:" at 2248,-655.67 h60
  text ".PRJ_Number" at 2793.5,-655.67 h60
  text "REV:" at 3638,-655.67 h60
  text ".PCB_Rev" at 3929.5,-655.67 h60
  text "SVN REV:" at 4476,-655.67 h60
  text ".VersionControl_RevNumber" at 4982,-655.67 h60
  text "TID #:" at 2248,-859 h60
  text ".TID" at 2793.5,-859 h60
  text "PLOT NAME =" at -228.5,-1064.34 h60
  text ".plot_File_Name" at 577,-1064.34 h60
  text "GENERATED    :" at 2250,-1064.34 h60
  text ".Print_Date" at 3119.5,-1064.34 h60
  text ".Print_Time" at 3848.5,-1064.34 h60
  text "TEXAS INSTRUMENTS" at 5113,-1064.34 h60
M6 Assembly Bottom:
  lines w10: -292.5,-727.33 6309.5,-727.33 ; -290.5,-930.67 6309.5,-930.67 ; 1115.5,-1140.5 1115.5,-937.67 ; 1737.5,-727.33 1737.5,-524 ; 2577.5,-727.33 2577.5,-524 ; 3844.5,-1134 3844.5,-524 ; 4733.5,-1134 6309,-1134 6309,-524 -292.5,-524 -292.5,-1134 2304.5,-1134 6309.5,-1134 6309.5,-524
  text "COMPONENTS MARKED 'DNP' SHOULD NOT BE POPULATED." at 6102,-318 h60
  text ".VariantName" at 5058,-434 h60
  text "ASSEMBLY VARIANT:" at 6097,-434 h60
  text ".VersionControl_RevNumber" at 1035.5,-656.17 h60
  text "SVN REV:" at 1541.5,-656.17 h60
  text ".PCB_Rev" at 2088,-656.17 h60
  text "REV:" at 2379.5,-656.17 h60
  text ".PRJ_Number" at 3224,-656.17 h60
  text "BOARD #:" at 3769.5,-656.17 h60
  text "PCB VIEWED FROM BOTTOM SIDE" at 6246,-656.17 h60
  text ".TID" at 3224,-859.5 h60
  text "TID #:" at 3769.5,-859.5 h60
  text "TEXAS INSTRUMENTS" at 904.5,-1064.84 h60
  text ".Print_Time" at 2169,-1064.84 h60
  text ".Print_Date" at 2898,-1064.84 h60
  text "GENERATED    :" at 3767.5,-1064.84 h60
  text ".plot_File_Name" at 5440.5,-1064.84 h60
  text "PLOT NAME =" at 6246,-1064.84 h60
M9 Title Sheet:
  drawing of 55 lines, arcs and shapes, not listed
  text "1" at 739.84,8036.5 h70
  text "2" at 3235.5,8036.5 h70
  text "3" at 5724.84,8036.5 h70
  text "4" at 8231.51,8036.5 h70
  text "5" at 10730.5,8036.5 h70
  text "6" at 13235.5,8036.5 h70
  text "A" at -416.5,6893.5 h70
  text "A" at 14383.5,6893.5 h70
  text "B" at -416.5,4513.5 h70
  text "B" at 14383.5,4513.5 h70
  text "C" at -416.5,2138.5 h70
  text "C" at 14383.5,2138.5 h70
  text "PROJECT TITLE:" at 11343.5,277.5 h45
  text ".PRJ_Title" at 11393.5,144.17 h70
  text "DESIGNED FOR:" at 11343.5,-23.5 h45
  text ".PRJ_Customer" at 11393.5,-163.5 h70
  text "D" at -416.5,-231.5 h70
  text "D" at 14383.5,-231.5 h70
  text "FILE NAME:" at 11343.5,-323.5 h45
  text ".PCB_File_Name_No_Path" at 11393.5,-443.5 h70
  text "Texas Instruments (TI) and/or its licensors do not warrant the accuracy or completeness of this specification" at 6374,-605.34 h45
  text "ENGINEER:" at 11343.5,-613.5 h45
  text "LAYOUT BY:" at 12848.5,-613.5 h45
  text "or any information contained therein. TI and/or its licensors do not warrant that this design will meet" at 6329.01,-718 h45
  text ".PRJ_Engineer" at 11393.5,-768.49 h70
  text ".PCB_Layout" at 12899,-768.49 h70
  text "the specifications, will be suitable for your application or fit for any particular purpose, or will operate in" at 6329.01,-830.67 h45
  text ".Layer_Name" at 577,-858.49 h60
  text "ALTIUM DESIGNER VERSION:" at 12848.5,-923.5 h45
  text "an implementation. TI and/or its licensors do not warrant that the design is production worthy. You should" at 6329.01,-943.33 h45
  text "completely validate and test your design implementation to confirm the system functionality for your application." at 6374,-1056 h45
  text ".print_Scale" at 11393.5,-1056.83 h70
  text ".Application_BuildNumber" at 12899,-1056.83 h70
  text "1" at 739.84,-1263.5 h70
  text "2" at 3235.5,-1263.5 h70
  text "3" at 5724.84,-1263.5 h70
  text "4" at 8231.51,-1263.5 h70
  text "5" at 10730.5,-1263.5 h70
  text "6" at 13235.5,-1263.5 h70
M10 Fab Notes:
  text ".Layer_Name" at 577,-858.49 h60
M11 Gerber Information:
  lines w10: -292,-930.17 6308,-930.17 ; -292,-726.83 6310,-726.83 ; -292,-523.5 -292,-1133.5 3713,-1133.5 6310,-1133.5 6310,-523.5 -291.5,-523.5 -291.5,-1133.5 1284,-1133.5 ; 2173,-1133.5 2173,-523.5 ; 3440,-726.83 3440,-523.5 ; 4280,-726.83 4280,-523.5 ; 4902,-1140 4902,-937.17
  text "ALL ARTWORK VIEWED FROM TOP SIDE" at -228.5,-655.67 h60
  text "BOARD #:" at 2248,-655.67 h60
  text ".PRJ_Number" at 2793.5,-655.67 h60
  text "REV:" at 3638,-655.67 h60
  text ".PCB_Rev" at 3929.5,-655.67 h60
  text "SVN REV:" at 4476,-655.67 h60
  text ".VersionControl_RevNumber" at 4982,-655.67 h60
  text "LAYER NAME =" at -228.5,-858.49 h60
  text "TID #:" at 2248,-859 h60
  text ".TID" at 2793.5,-859 h60
  text "PLOT NAME =" at -228.5,-1064.34 h60
  text ".plot_File_Name" at 577,-1064.34 h60
  text "GENERATED    :" at 2250,-1064.34 h60
  text ".Print_Date" at 3119.5,-1064.34 h60
  text ".Print_Time" at 3848.5,-1064.34 h60
  text "TEXAS INSTRUMENTS" at 5113,-1064.34 h60
M12 Stackup:
  text ".Layer_Name" at 577,-858.49 h60
M13 Component Bodies Top:
  text ".Layer_Name" at 577,-858.49 h60
M14 Component Bodies Bottom:
  text ".Layer_Name" at 577,-858.49 h60
M15 Courtyards Top:
  text ".Layer_Name" at 577,-858.49 h60
M16 Courtyards Bottom:
  text ".Layer_Name" at 577,-858.49 h60
Drill Drawing:
  text ".Layer_Name" at 577,-858.49 h60
M17 Embedded Cavity:
  text ".Layer_Name" at 577,-858.49 h60
M18 Embedded Assembly:
  text ".Layer_Name" at 577,-858.49 h60
M19 Embedded Keepout:
  text ".Layer_Name" at 577,-858.49 h60

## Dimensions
0,-400 to 1000,-400 on M2 Board Dimensions
0,0 to 0,5400 on M2 Board Dimensions
0,0 to 4575,0 on M2 Board Dimensions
